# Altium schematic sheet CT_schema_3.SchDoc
size 218 x 258 mm
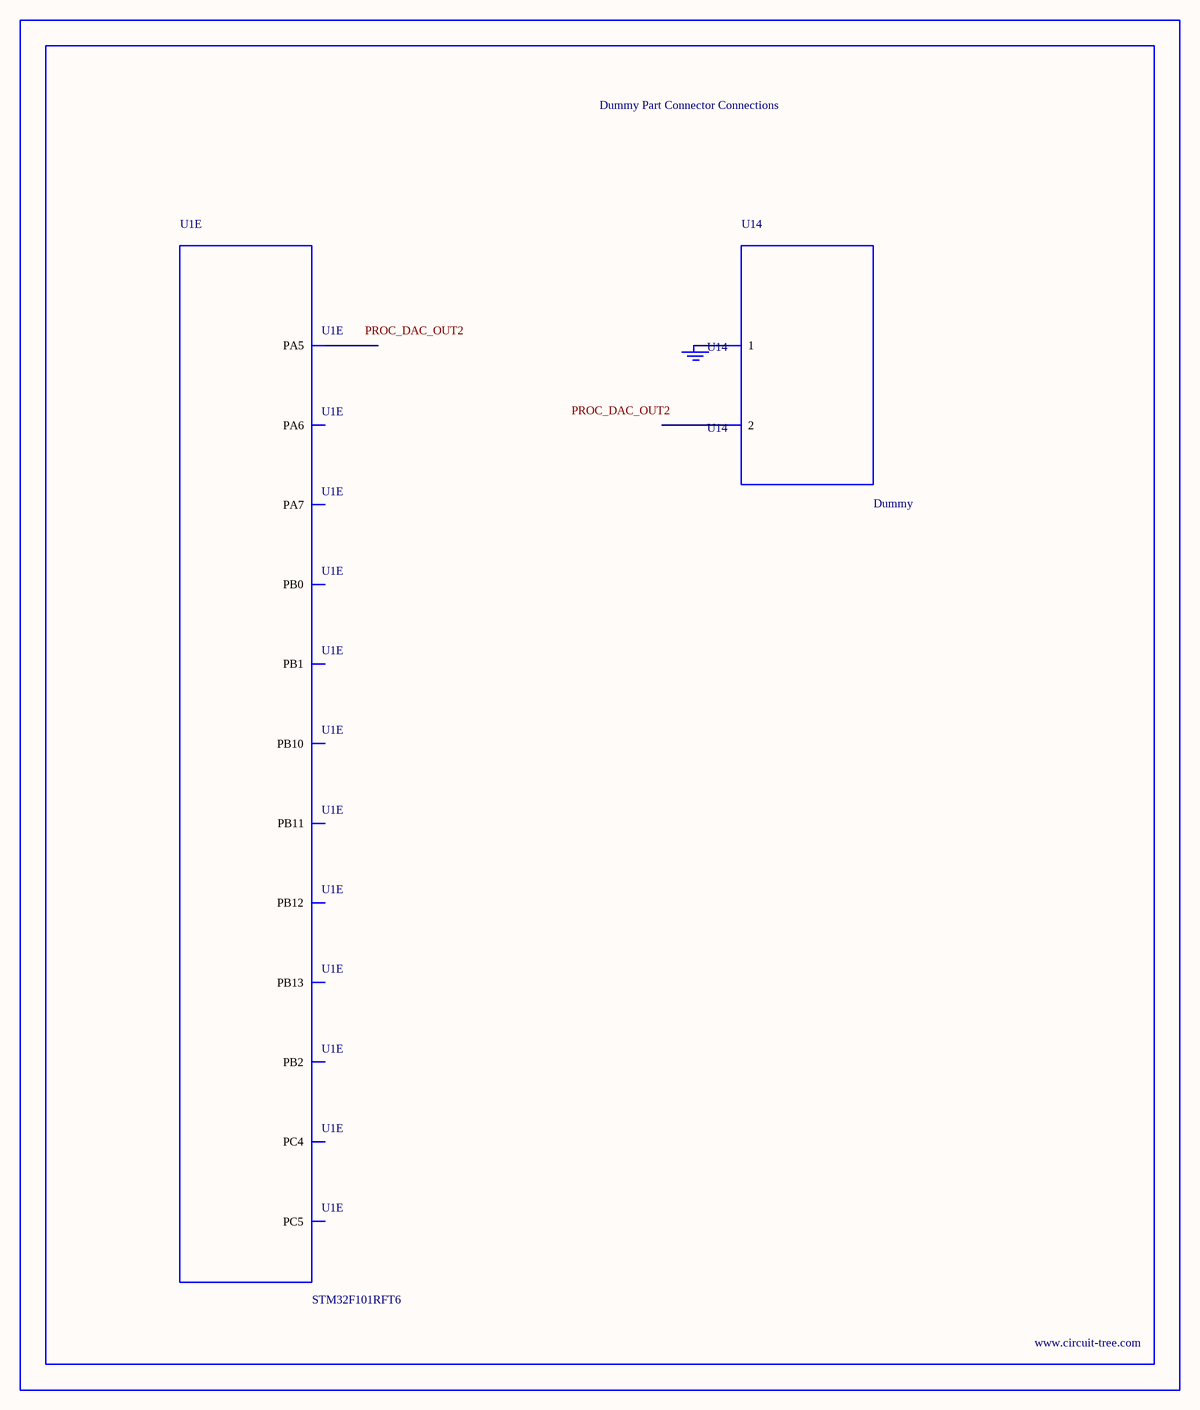
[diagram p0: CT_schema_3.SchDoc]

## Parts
BORDER2  (no value)
GND_INSTANCE_2_0  (no value)
U1  STM32F101RFT6  [LQFP64]  (part E of 5)
U14  Dummy  [DUMMY_PACKAGE_113]

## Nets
NetGND_INSTANCE_2_0_0: GND_INSTANCE_2_0.0(GND) U14.1

Not connected (* = marked no-connect by the designer): U1 21(PA5) 22(PA6) 23(PA7) 24(PC4) 25(PC5) 26(PB0) 27(PB1) 28(PB2) 29(PB10) 30(PB11) 33(PB12) 34(PB13); U14 2

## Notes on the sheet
- Labels drawn without touching a wire or pin: PROC_DAC_OUT2

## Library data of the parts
BORDER2 = BORDER_PAGE2
GND_INSTANCE_2_0 = GND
